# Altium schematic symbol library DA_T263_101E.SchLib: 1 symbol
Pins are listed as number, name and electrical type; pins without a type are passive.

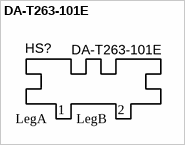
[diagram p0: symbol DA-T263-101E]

## DA-T263-101E
designator HS?
D2PAK Heatsink; Manufacturer: Ohmite
footprint DA-T263-101E (D2PAK Heatsink)
pins: 1 LegA, 2 LegB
